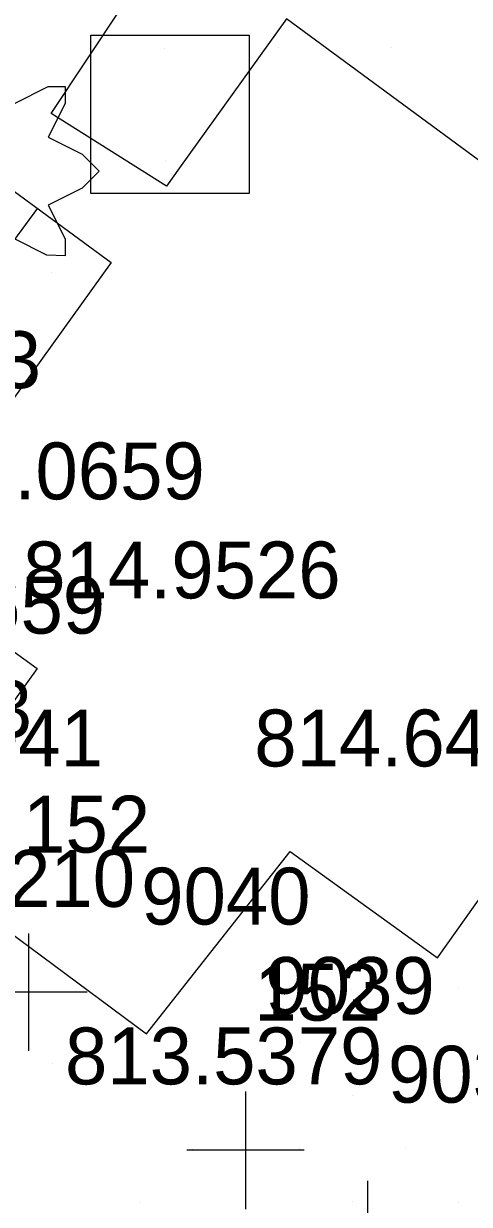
# Model space of a CAD drawing. Extents: x 1602514 to 1609837, y 863887 to 871157.
# Drawn here: x 1605135.1 to 1605194.3, y 866899.3 to 867056.2 of the extents above; entities that cross this region are included whole.
import ezdxf

# ---------------------------------------------------------------- set-up
doc = ezdxf.new("R2010")
doc.units = 0
for name, color, linetype in [('Environmental-New trees', 7, 'Continuous'), ('Survey-Buildings', 7, 'Continuous'), ('Survey-Sidewalks', 7, 'Continuous'), ('Survey-Spot concrete', 7, 'Continuous'), ('Survey-Spot dirt', 7, 'Continuous'), ('Survey-Text-Elevation', 7, 'Continuous'), ('Survey-Text-Feature', 7, 'Continuous'), ('Survey-Text-Name and Number', 7, 'Continuous'), ('Utility-Pole', 7, 'Continuous')]:
    doc.layers.add(name, color=color, linetype=linetype)

msp = doc.modelspace()

# ---------------------------------------------------------------- linework, layer by layer
at = {"layer": 'Environmental-New trees'}
msp.add_lwpolyline([(1605133.88, 867045.59), (1605138.38, 867047.84), (1605140.63, 867047.84), (1605140.63, 867045.59), (1605138.38, 867041.09), (1605142.88, 867038.84), (1605145.13, 867036.59), (1605142.88, 867034.34), (1605138.38, 867032.09), (1605140.63, 867027.59), (1605140.63, 867025.34), (1605138.2, 867025.42), (1605133.88, 867027.59)], dxfattribs=at)
msp.add_lwpolyline([(1605133.88, 867045.59), (1605138.38, 867047.84), (1605140.63, 867047.84), (1605140.63, 867045.59), (1605138.38, 867041.09), (1605142.88, 867038.84), (1605145.13, 867036.59), (1605142.88, 867034.34), (1605138.38, 867032.09), (1605140.63, 867027.59), (1605140.63, 867025.34), (1605138.2, 867025.42), (1605133.88, 867027.59)], dxfattribs=at)
at = {"layer": 'Survey-Buildings'}
for points in [[(1605190.06, 866932.05), (1605241.42, 867004.29), (1605170.03, 867056.81), (1605155.81, 867037.05), (1605154.06, 867034.61), (1605138.78, 867044.23), (1605166.94, 867086.69), (1605169.84, 867084.69), (1605184.21, 867105.16), (1605132.01, 867142.68), (1605116.66, 867120.43), (1605129.33, 867112.32), (1605120.65, 867099.05), (1605101.98, 867070.67), (1605103.93, 867068.47), (1605097.48, 867060.65), (1605146.75, 867024.45), (1605117.85, 866984.27), (1605136.88, 866970.51)], [(1605190.06, 866932.05), (1605241.42, 867004.29), (1605170.03, 867056.81), (1605155.81, 867037.05), (1605154.06, 867034.61), (1605138.78, 867044.23), (1605166.94, 867086.69), (1605169.84, 867084.69), (1605184.21, 867105.16), (1605132.01, 867142.68), (1605116.66, 867120.43), (1605129.33, 867112.32), (1605120.65, 867099.05), (1605101.98, 867070.67), (1605103.93, 867068.47), (1605097.48, 867060.65), (1605146.75, 867024.45), (1605117.85, 866984.27), (1605136.88, 866970.51)], [(1605136.88, 866970.51), (1605119.18, 866945.87), (1605151.43, 866921.93), (1605170.49, 866946.2), (1605190.06, 866932.05)], [(1605136.88, 866970.51), (1605119.18, 866945.87), (1605151.43, 866921.93), (1605170.49, 866946.2), (1605190.06, 866932.05)]]:
    msp.add_lwpolyline(points, dxfattribs=at)
at = {"layer": 'Survey-Sidewalks'}
msp.add_lwpolyline([(1605136.96, 867031.65), (1605124.78, 867015.14), (1605108.11, 867030.33), (1605110.82, 867034.92), (1605118.67, 867045.08)], dxfattribs=at)
msp.add_lwpolyline([(1605136.96, 867031.65), (1605124.78, 867015.14), (1605108.11, 867030.33), (1605110.82, 867034.92), (1605118.67, 867045.08)], dxfattribs=at)
at = {"layer": 'Survey-Spot concrete'}
for p, q in [((1605135.74, 866935.29), (1605135.74, 866919.67)), ((1605143.56, 866927.48), (1605127.93, 866927.48)), ((1605164.57, 866914.28), (1605164.57, 866898.66)), ((1605172.38, 866906.47), (1605156.76, 866906.47)), ((1605180.76, 866902.4), (1605180.76, 866886.77))]:
    msp.add_line(p, q, dxfattribs=at)
at = {"layer": 'Survey-Spot dirt'}
for p, q in [((1605153.84, 867052.94), (1605153.84, 867052.94)), ((1605153.84, 867052.94), (1605153.84, 867052.94)), ((1605168.94, 867053), (1605168.94, 867053)), ((1605168.94, 867053), (1605168.94, 867053)), ((1605183.99, 867053), (1605183.99, 867053)), ((1605183.99, 867053), (1605183.99, 867053)), ((1605153.88, 867038.03), (1605153.88, 867038.03)), ((1605153.88, 867038.03), (1605153.88, 867038.03)), ((1605138.82, 867023.07), (1605138.82, 867023.07)), ((1605138.82, 867023.07), (1605138.82, 867023.07)), ((1605185.87, 866935.03), (1605185.87, 866935.03)), ((1605185.87, 866935.03), (1605185.87, 866935.03)), ((1605178.69, 866927.87), (1605178.69, 866927.87)), ((1605178.69, 866927.87), (1605178.69, 866927.87)), ((1605192.9, 866927.93), (1605192.9, 866927.93)), ((1605192.9, 866927.93), (1605192.9, 866927.93)), ((1605171.75, 866920.81), (1605171.75, 866920.81)), ((1605171.75, 866920.81), (1605171.75, 866920.81)), ((1605185.79, 866920.84), (1605185.79, 866920.84)), ((1605185.79, 866920.84), (1605185.79, 866920.84)), ((1605138.97, 866918), (1605138.97, 866918)), ((1605138.97, 866918), (1605138.97, 866918)), ((1605164.5, 866913.91), (1605164.5, 866913.91)), ((1605164.5, 866913.91), (1605164.5, 866913.91)), ((1605178.78, 866913.76), (1605178.78, 866913.76)), ((1605178.78, 866913.76), (1605178.78, 866913.76)), ((1605192.83, 866913.75), (1605192.83, 866913.75)), ((1605192.83, 866913.75), (1605192.83, 866913.75)), ((1605157.49, 866906.64), (1605157.49, 866906.64)), ((1605157.49, 866906.64), (1605157.49, 866906.64)), ((1605171.69, 866906.71), (1605171.69, 866906.71)), ((1605171.69, 866906.71), (1605171.69, 866906.71)), ((1605185.79, 866906.69), (1605185.79, 866906.69)), ((1605185.79, 866906.69), (1605185.79, 866906.69)), ((1605150.51, 866899.52), (1605150.51, 866899.52)), ((1605150.51, 866899.52), (1605150.51, 866899.52)), ((1605164.62, 866899.65), (1605164.62, 866899.65)), ((1605164.62, 866899.65), (1605164.62, 866899.65)), ((1605178.76, 866899.69), (1605178.76, 866899.69)), ((1605178.76, 866899.69), (1605178.76, 866899.69)), ((1605192.89, 866899.6), (1605192.89, 866899.6)), ((1605192.89, 866899.6), (1605192.89, 866899.6))]:
    msp.add_line(p, q, dxfattribs=at)
at = {"layer": 'Utility-Pole'}
msp.add_lwpolyline([(1605144.04, 867054.64), (1605165.04, 867054.64), (1605165.04, 867033.64), (1605144.04, 867033.64)], close=True, dxfattribs=at)
msp.add_lwpolyline([(1605144.04, 867054.64), (1605165.04, 867054.64), (1605165.04, 867033.64), (1605144.04, 867033.64)], close=True, dxfattribs=at)

# ---------------------------------------------------------------- texts
at = {"layer": 'Survey-Text-Elevation'}
for s, p in [('815.1473', (1605095.24, 867007.75)), ('815.1473', (1605095.24, 867007.75)), ('815.0659', (1605117, 866992.97)), ('815.0659', (1605117, 866992.97)), ('814.9526', (1605135.04, 866979.81)), ('814.9526', (1605135.04, 866979.81)), ('814.4659', (1605103.76, 866975.13)), ('814.4659', (1605103.76, 866975.13)), ('814.2963', (1605094.04, 866961.34)), ('814.2963', (1605094.04, 866961.34)), ('814.6458', (1605165.74, 866957.48)), ('814.6458', (1605165.74, 866957.48)), ('813.9210', (1605107.74, 866938.82)), ('813.9210', (1605107.74, 866938.82)), ('813.5379', (1605140.6, 866915.23)), ('813.5379', (1605140.6, 866915.23))]:
    msp.add_text(s, height=7.56, dxfattribs=at).set_placement(p)
at = {"layer": 'Survey-Text-Feature'}
for p in [(1605135.04, 866946.03), (1605135.04, 866946.03), (1605165.74, 866923.7), (1605165.74, 866923.7)]:
    msp.add_text('152', height=7.56, dxfattribs=at).set_placement(p)
at = {"layer": 'Survey-Text-Name and Number'}
for s, p in [('9041', (1605123.14, 866957.48)), ('9041', (1605123.14, 866957.48)), ('9040', (1605150.72, 866936.47)), ('9040', (1605150.72, 866936.47)), ('9039', (1605167.22, 866924.59)), ('9039', (1605167.22, 866924.59)), ('9038', (1605183.5, 866912.8)), ('9038', (1605183.5, 866912.8))]:
    msp.add_text(s, height=7.56, dxfattribs=at).set_placement(p)

doc.saveas('drawing.dxf')
